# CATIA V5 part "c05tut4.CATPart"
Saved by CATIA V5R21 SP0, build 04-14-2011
Part number: Part1
Bounding box of the stored display mesh (mm): x 0 to 150, y -16 to 50, z 0 to 74.999
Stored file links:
  D:\CATIA V5R21 E-RESOURCES\CATIA-V5R21\catia-v5r21-prt\c05-catia-v5r20-prt\catia-v5r21-tut-04.CATPart
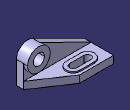
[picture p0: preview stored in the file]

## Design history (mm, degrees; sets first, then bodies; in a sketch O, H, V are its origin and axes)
Body1 (main body)
  Set1
    Sketch1 on xy-plane, origin (0, 0, 0), H (1, 0, 0), V (0, 1, 0)
      line L1 (0, 0) -> (0, 50)
      line L2 (0, 50) -> (75, 50)
      line L3 (75, 50) -> (150, 0)
      point P3 (150, 0)
      line L4 (150, 0) -> (0, 0)
      length L4 = 150
      length L1 = 50
      length L2 = 75
      vertical: L1 V
      horizontal: L2 H, L4 H
      coincidence: P3 H
  Pad1: profile Sketch1, direction (0, 0, 1), length 16
  Sketch2 on end face of Pad1, origin (0, 0, 16), H (1, 0, 0), V (0, 1, 0)
    construction line L1 (36, 28) -> (68, 28)
    point P1 (36, 28)
    line L2 (36, 44) -> (68, 44)
    line L3 (68, 12) -> (36, 12)
    arc A1 centre (68, 28) radius 16 from (68, 44) to (68, 12) cw
    arc A2 centre (36, 28) radius 16 from (36, 12) to (36, 44) cw
    reference projected line E1 (0, 50) -> (0, 0) from edge [face of Pad1 from Sketch1.L1 | end face of Pad1]
    reference projected line E2 (0, 0) -> (150, 0) from edge [face of Pad1 from Sketch1.L4 | end face of Pad1]
    distance P1 E1 = 36
    distance L3 E2 = 12
    radius A1 = 16
    length L2 = 32
    horizontal: L1 H
    tangency: A1 L2, A2 L2, A1 L3, A2 L3
  Pad2: profile Sketch2, direction (0, 0, 1), length 3
  Sketch3 on zx-plane, origin (0, 0, 0), H (-1, 0, 0), V (0, 0, 1)
    point P1 (-150, 0)
    line L1 (-150, 0) -> (-150, 50)
    arc A1 centre (-125, 50) radius 25 from (-150, 50) to (-113.9062, 72.4037) cw
    line L2 (-113.9062, 72.4037) -> (0, 16)
    point P5 (0, 16)
    line L3 (0, 16) -> (0, 0)
    line L4 (0, 0) -> (-150, 0)
    reference projected line E1 (-150, 0) -> (-150, 16) from edge [face of Pad1 from Sketch1.L3 | face of Pad1 from Sketch1.L4]
    length L1 = 50
    radius A1 = 25
    length L3 = 16
    coincidence: P1 H, P5 V, E1 L1
    vertical: L1 V, L3 V
    tangency: A1 L1, A1 L2
    horizontal: L4 H
  Pad3: profile Sketch3, direction (0, -1, 0), length 16
  Sketch4 on start face of Pad3, origin (0, 0, 0), H (-1, 0, 0), V (0, 0, 1)
    circle A1 centre (-125, 50) radius 25
    reference projected arc E1 centre (-125, 50) radius 25 from (-113.9062, 72.4037) to (-150, 50) ccw from edge [face of Pad3 from Sketch3.A1 | start face of Pad3]
    radius A1 = 25
    concentricity: A1 E1
  Pad4: profile Sketch4, direction (0, 1, 0), length 9
  Sketch5 on end face of Pad4, origin (0, 9, 0), H (-1, 0, 0), V (0, 0, 1)
    circle A1 centre (-125, 50) radius 12.5
    reference projected circle E1 centre (-125, 50) radius 25 from edge [face of Pad4 from Sketch4.A1 | end face of Pad4]
    radius A1 = 12.5
    concentricity: A1 E1
  Sketch6 on end face of Pad2, origin (0, 0, 19), H (1, 0, 0), V (0, 1, 0)
    construction line L1 (36, 28) -> (68, 28)
    line L2 (36, 36) -> (68, 36)
    line L3 (68, 20) -> (36, 20)
    arc A1 centre (68, 28) radius 8 from (68, 36) to (68, 20) cw
    arc A2 centre (36, 28) radius 8 from (36, 20) to (36, 36) cw
    reference projected arc E1 centre (36, 28) radius 16 from (36, 44) to (36, 12) ccw from edge [face of Pad2 from Sketch2.A2 | end face of Pad2]
    reference projected arc E2 centre (68, 28) radius 16 from (68, 12) to (68, 44) ccw from edge [face of Pad2 from Sketch2.A1 | end face of Pad2]
    distance L1 L2 = 8
    horizontal: L1 H
    tangency: A1 L2, A2 L2, A1 L3, A2 L3
    concentricity: A2 E1, A1 E2
  Pocket1: profile Sketch6, direction (0, 0, -1), through (limit type 3)
  Pocket2: profile Sketch5, direction (0, -1, 0), through (limit type 3)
